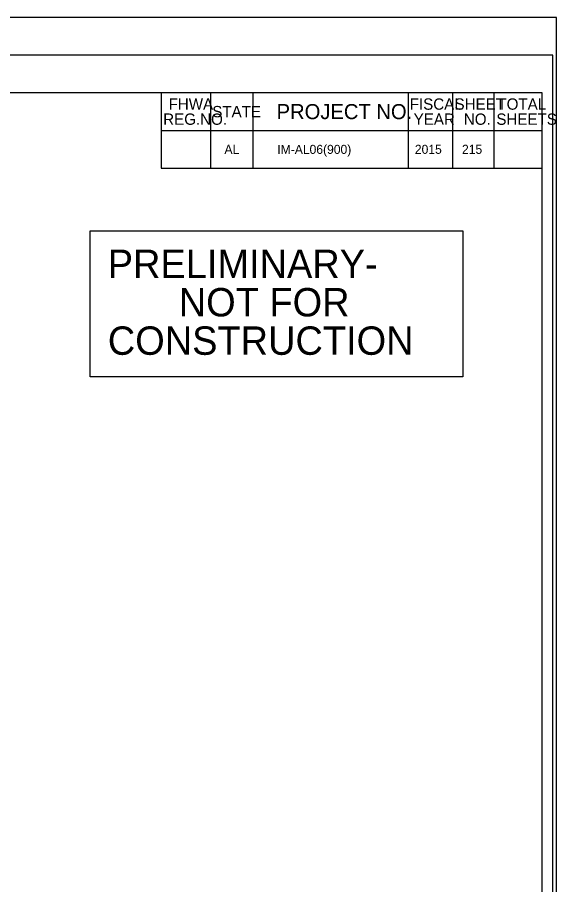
# Model space of a CAD drawing. Extents: x 504255 to 505955, y 659986 to 661086.
# Drawn here: x 505613 to 505955, y 660536 to 661086 of the extents above; entities that cross this region are included whole.
import ezdxf

# ---------------------------------------------------------------- set-up
doc = ezdxf.new("R2010")
doc.units = 0
for name, color, linetype in [('1', 7, 'Continuous'), ('Level 62', 7, 'Continuous'), ('Level1', 7, 'Continuous'), ('Level5', 7, 'Continuous')]:
    doc.layers.add(name, color=color, linetype=linetype)

msp = doc.modelspace()

# ---------------------------------------------------------------- linework, layer by layer
at = {"layer": '1'}
msp.add_lwpolyline([(505659.62, 660950.97), (505896.03, 660950.97), (505896.03, 660858.34), (505659.62, 660858.34)], close=True, dxfattribs=at)
at = {"layer": 'Level 62'}
msp.add_lwpolyline([(505955.48, 661086.39), (504255.48, 661086.39), (504255.48, 659986.39), (505955.48, 659986.39)], close=True, dxfattribs=at)
at = {"layer": 'Level1'}
for p, q in [((505735.94, 661038.56), (505735.94, 660990.73)), ((505762.85, 661038.58), (505762.85, 660990.75)), ((505861.26, 661038.56), (505861.26, 660990.74)), ((505889.53, 661038.57), (505889.53, 660990.74)), ((505915.54, 661038.57), (505915.54, 660990.75)), ((505946.29, 661038.56), (505946.29, 661038.56)), ((505946.29, 661033.78), (505946.29, 661033.78)), ((505704.76, 661014.65), (505946.29, 661014.65))]:
    msp.add_line(p, q, dxfattribs=at)
for points in [[(504257.9, 660010.3), (505953.07, 660010.3), (505953.07, 661062.47), (504257.9, 661062.47), (504257.9, 660010.3)], [(504327.92, 660023.67), (505946.29, 660023.67), (505946.29, 661038.56), (504327.92, 661038.56), (504327.92, 660023.67)], [(505704.76, 660990.74), (505946.29, 660990.74), (505946.29, 661038.56), (505704.76, 661038.56), (505704.76, 660990.74)]]:
    msp.add_lwpolyline(points, dxfattribs=at)

# ---------------------------------------------------------------- texts
at = {"layer": '1'}
for s, p in [('PRELIMINARY-', (505670.79, 660921.09)), ('NOT FOR', (505715.83, 660896.74)), ('CONSTRUCTION', (505670.83, 660872.39))]:
    msp.add_text(s, height=18, rotation=360, dxfattribs=at).set_placement(p)
at = {"layer": 'Level1'}
for s, height, p in [('FHWA', 7.174, (505709.39, 661027.81)), ('FISCAL', 7.174, (505862.3, 661027.81)), ('SHEET', 7.174, (505890.72, 661027.81)), ('TOTAL', 7.174, (505917.91, 661027.81)), ('STATE', 7.174, (505737.07, 661023.02)), ('PROJECT NO.', 9.5652, (505777.9, 661021.83)), ('REG.NO.', 7.174, (505705.96, 661018.24)), ('YEAR', 7.174, (505864.81, 661018.24)), ('NO.', 7.174, (505896.63, 661018.24)), ('SHEETS', 7.174, (505917.25, 661018.24))]:
    msp.add_text(s, height=height, dxfattribs=at).set_placement(p)
at = {"layer": 'Level5'}
for s, height, p in [('AL', 5.739, (505744.82, 660999.83)), ('IM-AL06(900)', 5.7391, (505778.33, 660999.79)), ('2015', 5.739, (505865.57, 660999.83)), ('215', 5.739, (505895.45, 660999.83))]:
    msp.add_text(s, height=height, dxfattribs=at).set_placement(p)

doc.saveas('drawing.dxf')
